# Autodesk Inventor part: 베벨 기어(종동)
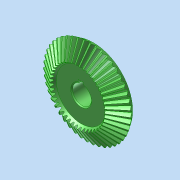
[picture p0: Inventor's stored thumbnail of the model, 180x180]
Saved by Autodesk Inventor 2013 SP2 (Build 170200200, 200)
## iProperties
Created: 2026-01
Part Number: 베벨 기어(종동)
Material: Generic
Document SubType Name: Modeling
Designer: a
Density: 1 g/cm^3
Author: a
변환 표준: STEP AP214IS
전처리기: Build: 200, Release: 2013 SP2 Update 6 - Date: Thu 07/17/2014
전송 단위: 밀리미터
불확실성: 0.01
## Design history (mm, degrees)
node "베벨 기어(종동)1"
body "Solid1"
node "기준1"
